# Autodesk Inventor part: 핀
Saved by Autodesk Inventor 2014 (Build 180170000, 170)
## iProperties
Created: 2024-08
Part Number: 핀
Material: 일반
Document SubType Name: Modeling
Designer: dg
Density: 1 g/cm^3
Appearance: 기본값
Author: dg
Author: jhkim
Creation Date: 2024-08-09
Sending System: Autodesk Inventor 2025
Preprocessor: ST-DEVELOPER v20
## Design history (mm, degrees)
node "핀1"
node "솔리드1"
node "기준1"
